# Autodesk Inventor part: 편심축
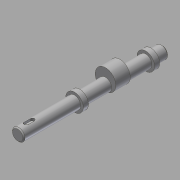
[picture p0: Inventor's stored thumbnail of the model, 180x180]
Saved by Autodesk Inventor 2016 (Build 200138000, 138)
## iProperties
Created: 2016-02
Part Number: 편심축
Material: 강철, 연강
Document SubType Name: Modeling
Designer: mduedu
Density: 1 g/cm^3
Appearance: 강철
Author: mduedu
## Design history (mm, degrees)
sketch "스케치1"
  geometry: C1 r 6 at (0, 0); 1 further point
  constraints: 1 centre point, 1 coincident
  dimensions: "d0" = 12 diameter of C1
extrude "돌출1" new body sketch "스케치1" distance "d1" = 140; taper "d2" = 0 deg
chamfer "모따기1" distance "d3" = 1; stored, may be unused: second distance "d4" = 2, angle "d5" = 45 deg
node "작업 평면1"
sketch "스케치2"
  geometry: C1 r 10 at (0, 4); C2 r 6 at (0, 0) reference; 1 further point
  constraints: 1 centre point, 1 tangent, 1 vertical alignment
  dimensions: "d7" = 20 diameter of C1
extrude "돌출2" join sketch "스케치2" stored distance "d8" = 14; taper "d9" = 0 deg
node "작업 평면2"
sketch "스케치3"
  geometry: C1 r 8.5 at (0, 0); 1 further point
  constraints: 1 centre point, 1 coincident
  dimensions: "d12" = 17 diameter of C1
extrude "돌출3" join sketch "스케치3" distance "d13" = 5; taper "d14" = 0 deg
node "작업 평면3"
sketch "스케치4"
  geometry: L1 (-5, 140)-(5, 140) reference; L2 (0, 140)-(0, 0); L3 (-2, 132)-(-2, 126); L4 (2, 126)-(2, 132); A1 r 2 centre (0, 132) between (2, 132) and (-2, 132); A2 r 2 centre (0, 126) between (-2, 126) and (2, 126)
  constraints: 6 end point, 4 point on circle, 4 tangent, 2 centre point, 2 point on line, 1 midpoint, 1 parallel, 1 perpendicular
  dimensions: "d15" = 4 distance between parallel lines of L3 L4; "d17" = 6 distance edge to line of A1 L1; "d18" = 10 dimension on A2 A1
extrude "돌출4" cut sketch "스케치4" distance "d19" = 2.5; taper "d20" = 0 deg
sketch "스케치5"
  geometry: L1 (6, 55)-(6, 139) reference; L2 (-6, 55)-(-6, 139) reference; L3 (6, 115)-(-6, 115); L4 (-5, 140)-(5, 140) reference; L5 (6, 116.5)-(4.5, 115); L6 (6, 116.5)-(6, 115); L7 (4.5, 115)-(6, 115); 1 further point
  constraints: 8 end point, 4 point on line, 2 collinear, 1 perpendicular
  dimensions: "d21" = 25 distance between parallel lines of L3 L4; "d22" = 3 diameter of L5.start L3; "d24" = 45 deg angle of L3 L5
revolve "회전1" sketch "스케치5" stored, may be unused: angle "d25" = 90 deg
sketch "스케치6"
  geometry: L1 (6, 116.5)-(4.5, 115) reference; L2 (6, 113.5)-(4.5, 115) reference; 2 further points
  constraints: 1 coincident
node "작업 평면4"
sketch "스케치7"
  geometry: C1 r 8.5 at (0, -4); 1 further point
  constraints: 1 centre point, 1 coincident
  dimensions: "d27" = 17 diameter of C1
extrude "돌출5" join sketch "스케치7" distance "d29" = 5; taper "d30" = 0 deg
node "솔리드1"
other parameters: "d6" = -48, "d11" = -11
